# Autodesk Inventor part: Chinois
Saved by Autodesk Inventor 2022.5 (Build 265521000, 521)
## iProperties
Created: 2024-07
Part Number: Chinois
Material: Generic
Document SubType Name: Modeling
Designer: AdminForWorker
Density: 1 g/cm^3
Appearance: Default
Title: Chinois
Author: AdminForWorker
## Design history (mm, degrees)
feature "Chinois"
body "Solid1"
